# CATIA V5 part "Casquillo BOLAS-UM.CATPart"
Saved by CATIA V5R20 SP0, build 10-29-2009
Part number: Casquillo BOLAS-UM
Revision: ANY
Definition: UNKNOWN
Nomenclature: Casquillo BOLAS-UM
Source: Unknown
Bounding box of the stored display mesh (mm): x -1.775 to 1.775, y 0 to 5, z -1.775 to 1.775
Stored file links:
  C:\Users\Utente\Desktop\IO LAVORO\3D X SITO CF\X SITO\3D files UM\UM043642 PRODUCT\Casquillo BOLAS-UM.CATPart
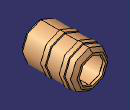
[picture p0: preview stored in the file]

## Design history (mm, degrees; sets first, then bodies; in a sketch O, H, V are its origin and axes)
Body1 "Chaflán3" (main body)
  Solid1: solid without history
